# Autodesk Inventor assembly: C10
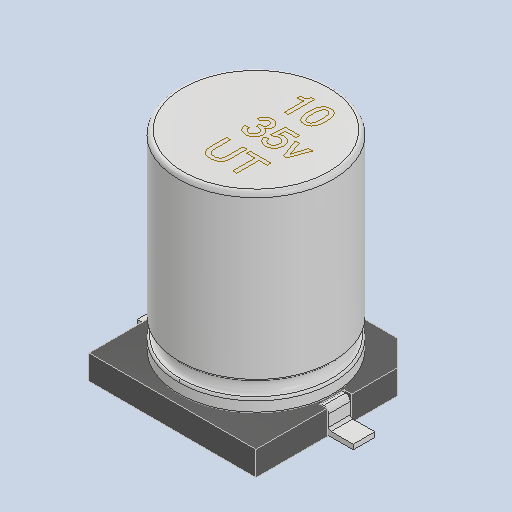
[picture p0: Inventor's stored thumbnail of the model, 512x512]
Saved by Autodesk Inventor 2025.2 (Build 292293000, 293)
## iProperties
Created: 2025-04
Part Number: C10
Description: PART--DESC
Document SubType Name: Assembly
Designer: BennF
Author: BennF
Revision Number: NONE
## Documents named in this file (4)
- C:\Users\BennF\Nextcloud\Benutzer\CNC JarBeRi\existing parts\Electronics\RepRap A4988 Shied (USE WITHOUT ARDUINO)\reprap-a4988-1.snapshot.1\RepRap\RepRap\C10_2.iam
- C:\Users\BennF\Nextcloud\Benutzer\CNC JarBeRi\existing parts\Electronics\RepRap A4988 Shied (USE WITHOUT ARDUINO)\reprap-a4988-1.snapshot.1\RepRap\RepRap\C10 Geometry.ipt
- C:\Users\BennF\Nextcloud\Benutzer\CNC JarBeRi\existing parts\Electronics\RepRap A4988 Shied (USE WITHOUT ARDUINO)\reprap-a4988-1.snapshot.1\RepRap\RepRap\bay2_2.iam
- C:\Users\BennF\Nextcloud\Benutzer\CNC JarBeRi\existing parts\Electronics\RepRap A4988 Shied (USE WITHOUT ARDUINO)\reprap-a4988-1.snapshot.1\RepRap\RepRap\name4.ipt
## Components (3 placed, 3 different names)
1. C10 Geometry
2. bay2 [sub-assembly]
3. name4
